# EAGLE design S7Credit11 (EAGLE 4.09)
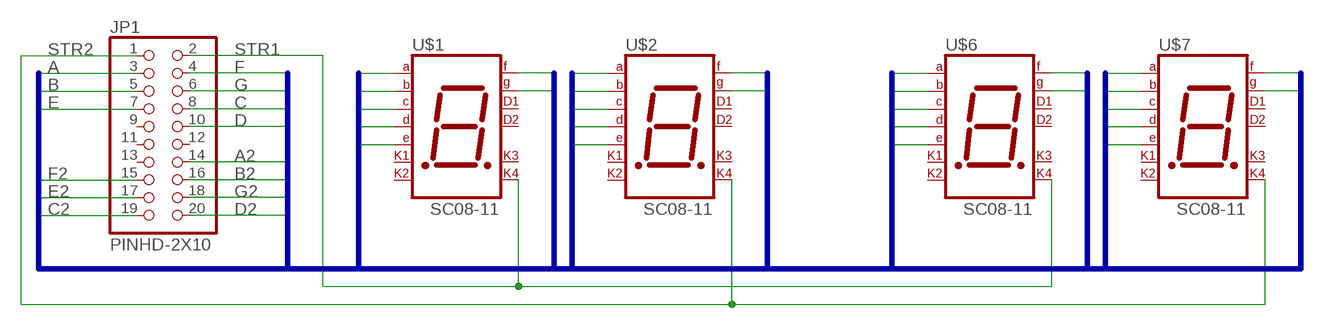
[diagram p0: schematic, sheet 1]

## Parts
JP1  PINHD-2X10  [2X10]
U$1  SC08-11  [SC08-11]
U$2  SC08-11  [SC08-11]
U$6  SC08-11  [SC08-11]
U$7  SC08-11  [SC08-11]

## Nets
A: JP1.3 U$1.1(A) U$2.1(A)
A2: JP1.14 U$6.1(A) U$7.1(A)
B: JP1.5 U$1.14(B) U$2.14(B)
B2: JP1.16 U$6.14(B) U$7.14(B)
C: JP1.8 U$1.12(C) U$2.12(C)
C2: JP1.19 U$6.12(C) U$7.12(C)
D: JP1.10 U$1.10(D) U$2.10(D)
D2: JP1.20 U$6.10(D) U$7.10(D)
E: JP1.7 U$1.4(E) U$2.4(E)
E2: JP1.17 U$6.4(E) U$7.4(E)
F: JP1.4 U$1.2(F) U$2.2(F)
F2: JP1.15 U$6.2(F) U$7.2(F)
G: JP1.6 U$1.13(G) U$2.13(G)
G2: JP1.18 U$6.13(G) U$7.13(G)
STR1: JP1.2 U$1.16(M4) U$6.16(M4)
STR2: JP1.1 U$2.16(M4) U$7.16(M4)
Unconnected: JP1.9 JP1.11 JP1.12 JP1.13 U$1.3(M1) U$1.5(M2) U$1.6(D1) U$1.9(D2) U$1.11(M3) U$2.3(M1) U$2.5(M2) U$2.6(D1) U$2.9(D2) U$2.11(M3) U$6.3(M1) U$6.5(M2) U$6.6(D1) U$6.9(D2) U$6.11(M3) U$7.3(M1) U$7.5(M2) U$7.6(D1) U$7.9(D2) U$7.11(M3)

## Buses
BUS:A,B,C,D,E,F,G,A2,B2,C2,D2,E2,F2,G2

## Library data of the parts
JP1 = PINHEAD:PINHD-2X10: PIN HEADER
U$1 U$2 U$6 U$7 = SPECIAL:SC08-11

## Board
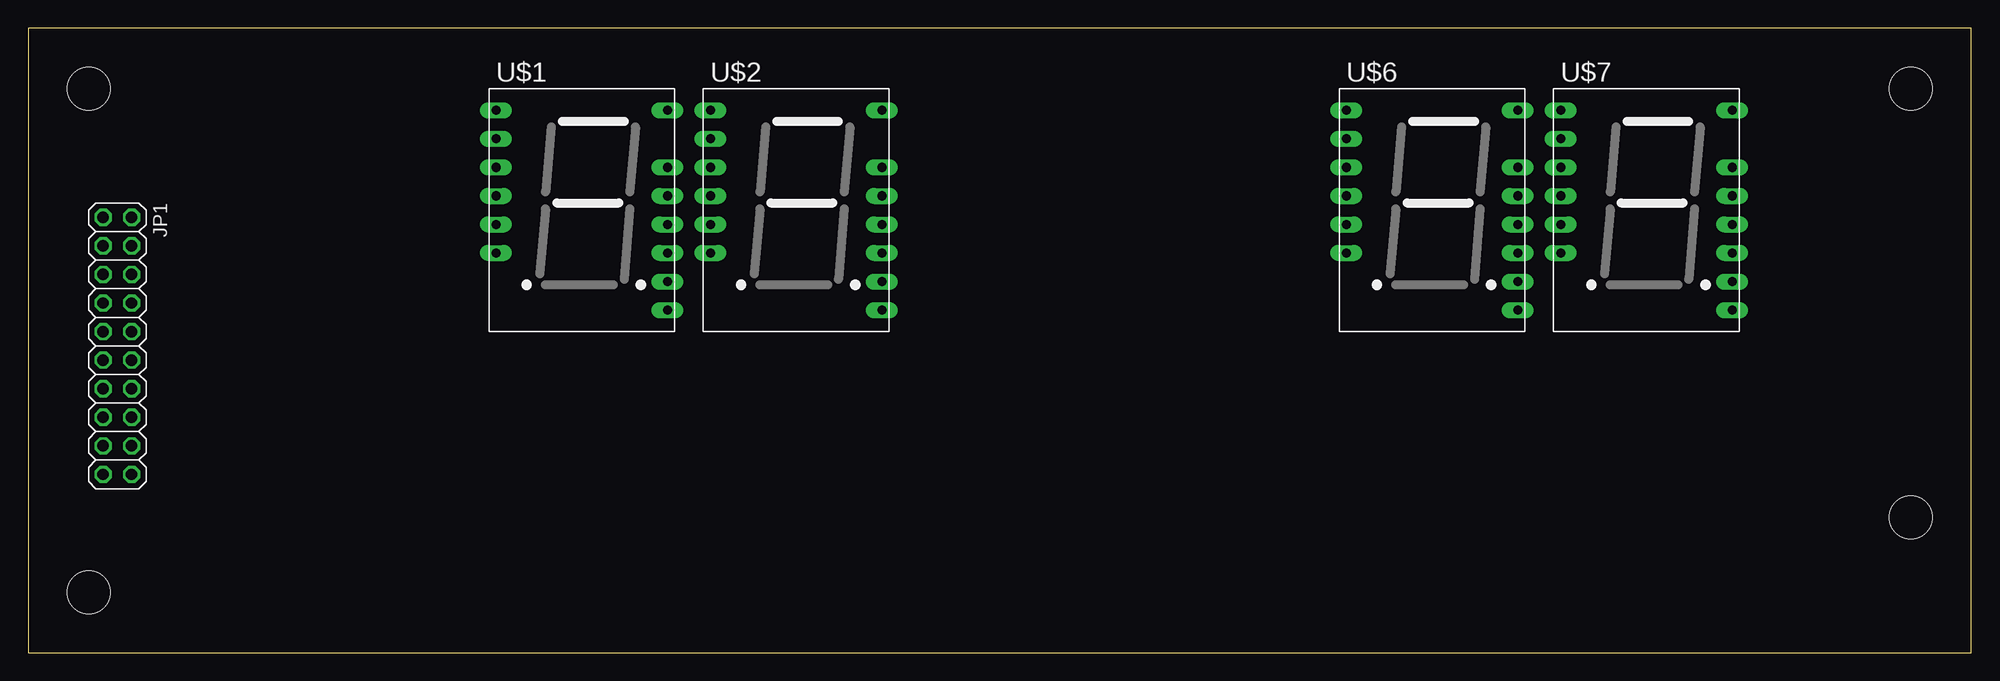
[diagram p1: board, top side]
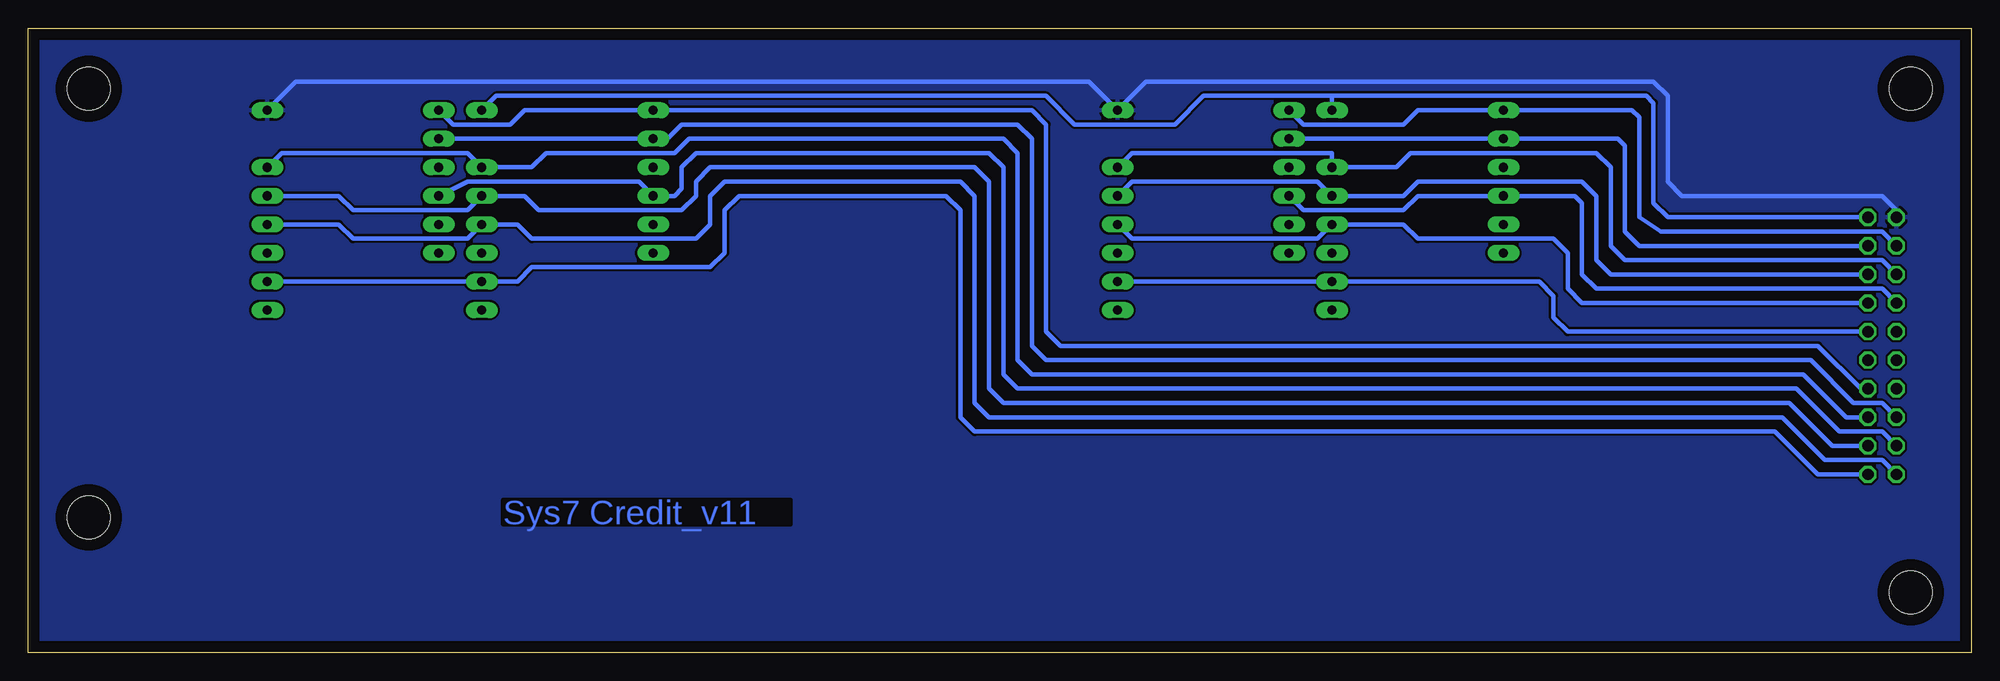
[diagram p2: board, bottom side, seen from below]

Size 172.7 x 55.55 mm. Coordinates in mm from the lower left corner, seen from the top.
Outline: 0,0 172.7,0 172.7,55.55 0,55.55 0,0
Copper layers used: Bottom
Holes 3.81 mm at 5.39,50.16 5.39,5.39 167.32,12.06 167.32,50.16
bKeepout: area 114,9.5 to 131.1,15.2

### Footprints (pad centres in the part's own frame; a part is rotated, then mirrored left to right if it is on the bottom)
2X10 = drill 1.016 octagon: 1 -11.43,-1.27; 2 -11.43,1.27; 3 -8.89,-1.27; 4 -8.89,1.27; 5 -6.35,-1.27; 6 -6.35,1.27; 7 -3.81,-1.27; 8 -3.81,1.27; 9 -1.27,-1.27; 10 -1.27,1.27; 11 1.27,-1.27; 12 1.27,1.27; 13 3.81,-1.27; 14 3.81,1.27; 15 6.35,-1.27; 16 6.35,1.27; 17 8.89,-1.27; 18 8.89,1.27; 19 11.43,-1.27; 20 11.43,1.27
SC08-11 = drill 0.813 pad 1.422 long: 1 -7.62,22.86; 2 -7.62,20.32; 3 -7.62,17.78; 4 -7.62,15.24; 5 -7.62,12.7; 6 -7.62,10.16; 9 7.62,5.08; 10 7.62,7.62; 11 7.62,10.16; 12 7.62,12.7; 13 7.62,15.24; 14 7.62,17.78; 16 7.62,22.86

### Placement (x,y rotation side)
JP1  7.93,27.3 270 top
U$1  49.21,25.39 0 top
U$2  68.26,25.39 0 top
U$6  124.77,25.39 0 top
U$7  143.82,25.39 0 top

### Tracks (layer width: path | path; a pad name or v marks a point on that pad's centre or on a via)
A
  Bottom 0.406: U$2.1 59.37,46.98 50.48,46.98 49.21,48.25 U$1.1 30.16,48.25 29.52,47.62 29.52,38.73 27.62,37.46 7.93,37.46 JP1.3
A2
  Bottom 0.406: U$7.1 134.93,46.98 129.85,46.98 128.58,48.25 U$6.1 83.5,48.25 82.23,46.98 82.23,28.57 80.96,27.3 13.65,27.3 9.84,23.49 JP1.14
B
  Bottom 0.406: U$2.14 74.61,44.44 56.83,44.44 U$1.14 51.11,43.17 49.84,44.44 33.33,44.44 32.06,43.17 32.06,36.19 30.79,34.92 7.93,34.92 JP1.5
B2
  Bottom 0.406: U$7.14 150.17,44.44 133.66,44.44 U$6.14 127.95,43.17 126.68,44.44 115.25,44.44 113.98,45.71 86.04,45.71 84.77,44.44 84.77,26.03 83.5,24.76 14.92,24.76 11.11,20.95 JP1.16
C
  Bottom 0.406: U$2.12 74.61,36.82 58.1,36.82 U$1.12 50.48,38.09 49.21,36.82 37.14,36.82 35.87,35.55 35.87,32.38 34.6,31.11 JP1.8
C2
  Bottom 0.406: U$7.12 145.09,38.09 143.82,36.82 133.66,36.82 U$6.12 129.22,38.09 127.95,36.82 113.34,36.82 112.07,38.09 112.07,40.63 110.8,41.9 89.85,41.9 88.58,40.63 88.58,22.22 87.31,20.95 16.82,20.95 13.01,17.14 7.93,17.14 JP1.19
D
  Bottom 0.406: U$2.10 U$1.10 38.41,33.01 37.14,31.74 37.14,29.84 35.87,28.57 JP1.10
D2
  Bottom 0.406: U$7.10 U$6.10 129.22,33.01 127.95,34.28 112.07,34.28 110.8,35.55 110.8,39.36 109.53,40.63 91.12,40.63 89.85,39.36 89.85,20.95 88.58,19.68 17.46,19.68 13.65,15.87 JP1.20
E
  Bottom 0.406: U$2.4 59.37,39.36 50.48,39.36 49.21,40.63 U$1.4 35.24,40.63 34.6,40 34.6,33.65 33.33,32.38 7.93,32.38 JP1.7
E2
  Bottom 0.406: U$7.4 133.66,41.9 118.42,41.9 U$6.4 115.25,40.63 114.61,41.27 114.61,43.17 113.34,44.44 87.31,44.44 86.04,43.17 86.04,24.76 84.77,23.49 15.55,23.49 11.74,19.68 7.93,19.68 JP1.17
F
  Bottom 0.406: U$2.2 U$1.2 31.43,45.71 30.79,45.08 30.79,37.46 29.52,36.19 JP1.4
F2
  Bottom 0.406: U$7.2 U$6.2 115.88,45.71 114.61,46.98 84.77,46.98 83.5,45.71 83.5,27.3 82.23,26.03 14.28,26.03 10.47,22.22 7.93,22.22 JP1.15
G
  Bottom 0.406: U$2.13 74.61,41.9 58.1,41.9 U$1.13 50.48,40.63 49.21,41.9 34.6,41.9 33.33,40.63 33.33,34.92 32.06,33.65 JP1.6
G2
  Bottom 0.406: U$7.13 145.09,40.63 143.82,39.36 133.66,39.36 U$6.13 128.58,40.63 127.31,39.36 114.61,39.36 113.34,40.63 113.34,41.9 112.07,43.17 88.58,43.17 87.31,41.9 87.31,23.49 86.04,22.22 16.19,22.22 12.38,18.41 JP1.18
STR1
  Bottom 0.406: 56.83,49.52 U$1.16 | 56.83,49.52 68.26,49.52 70.8,46.98 79.69,46.98 82.23,49.52 131.12,49.52 U$6.16 | 56.83,49.52 28.89,49.52 28.25,48.89 28.25,40 26.98,38.73 JP1.2
STR2
  Bottom 0.406: U$7.16 148.9,50.79 78.42,50.79 U$2.16 73.34,50.79 28.25,50.79 26.98,49.52 26.98,41.9 25.71,40.63 7.93,40.63 6.66,39.36 JP1.1
  pour Bottom: -0.16,55.56 172.56,55.56 172.72,-0.01 0,-0.01

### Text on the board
Bottom: Sys7 Credit_v11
